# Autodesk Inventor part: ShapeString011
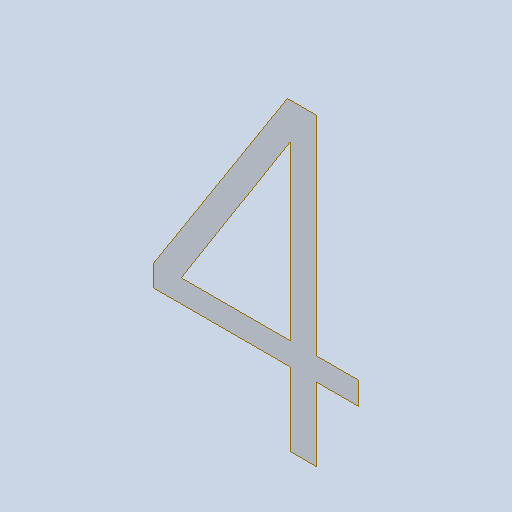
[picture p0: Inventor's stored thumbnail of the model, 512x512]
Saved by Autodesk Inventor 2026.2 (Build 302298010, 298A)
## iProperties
Created: 2026-10
Part Number: ShapeString011
Material: Générique
Document SubType Name: Modeling
Designer: mel
Density: 1 g/cm^3
Appearance: Par défaut
Author: mel
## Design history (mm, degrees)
feature "Composite1"
body "Srf1"
